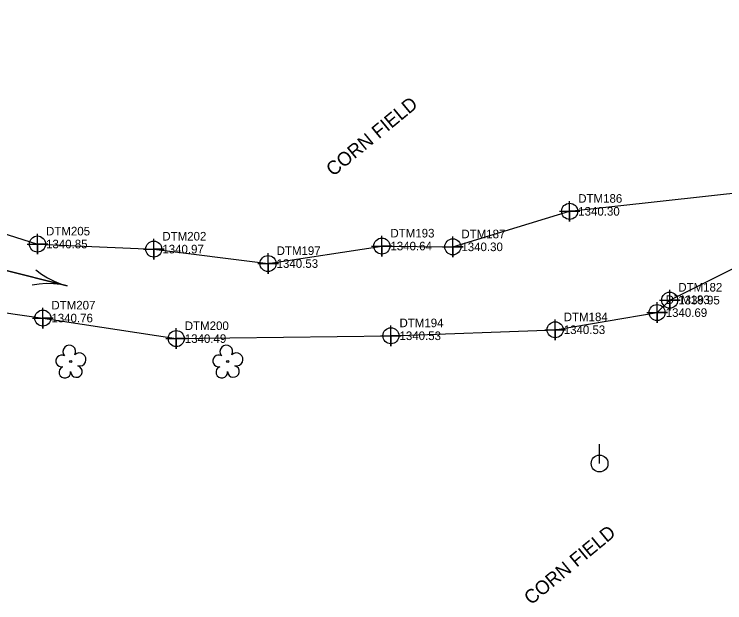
# Model space of a CAD drawing. Extents: x 1435573 to 1437263, y 981340 to 982884.
# Drawn here: x 1436335.7 to 1436542.7, y 982216.7 to 982388.1 of the extents above; entities that cross this region are included whole.
import ezdxf

# ---------------------------------------------------------------- set-up
doc = ezdxf.new("R2010")
doc.units = 0
for name, color, linetype in [('Exist Hydro Jurisdictional Stream or Body of Water', 7, 'Continuous'), ('Exist Hydro River Flow Arrow CELL', 7, 'Continuous'), ('Exist Hydro Stream or Body of Water Cogo Elevation', 7, 'Continuous'), ('Exist Hydro Stream or Body of Water Cogo Number', 7, 'Continuous'), ('Exist Hydro Stream or Body of Water Cogo Point CELL', 7, 'Continuous'), ('Exist Utilities Power Pole CELL', 7, 'Continuous'), ('Exist Vegetation Shrub Text', 7, 'Continuous'), ('Exist Vegetation Tree CELL', 7, 'Continuous')]:
    doc.layers.add(name, color=color, linetype=linetype)

# ---------------------------------------------------------------- blocks, each defined once
blk = doc.blocks.new('EXIST UTILITIES POWER POLE')
at = {"layer": 'Exist Utilities Power Pole CELL'}
for q in [(0, 0.1125), (0, 0)]:
    blk.add_line((0, 0), q, dxfattribs=at)
blk.add_circle((0, 0), 0.049, dxfattribs=at)
blk = doc.blocks.new('EXIST HYDRO RIVER FLOW ARROW')
at = {"layer": 'Exist Hydro River Flow Arrow CELL'}
blk.add_line((0, 0), (0, 0), dxfattribs=at)
blk.add_lwpolyline([(0, 0.04575), (0.03775, 0.03), (0.07725, 0.01725), (0.118, 0.00775), (0.159, 0.0015), (0.2, 0), (-0.2, 0), (0.2, 0), (0.159, -0.0015), (0.118, -0.00775), (0.07725, -0.01725), (0.03775, -0.03), (0, -0.04575)], dxfattribs=at)

msp = doc.modelspace()

# ---------------------------------------------------------------- linework, layer by layer
at = {"layer": 'Exist Hydro Jurisdictional Stream or Body of Water'}
for points in [[(1436111.15, 982453.74), (1436137.02, 982423.29), (1436156.59, 982404.89), (1436183.39, 982389.76), (1436202.59, 982381.74), (1436230.76, 982371.66), (1436265.68, 982349.11), (1436287.96, 982335.57), (1436310.38, 982331.33), (1436342.49, 982321.19), (1436376.37, 982319.71), (1436409.66, 982315.5), (1436442.82, 982320.6), (1436463.49, 982320.37), (1436497.53, 982330.71), (1436550.33, 982336.59), (1436616.17, 982332.31)], [(1436091.98, 982443.75), (1436118.69, 982406.49), (1436146.13, 982381.57), (1436167.28, 982362.75), (1436182.9, 982351.8), (1436221.27, 982335.17), (1436252.29, 982318.28), (1436286.21, 982313.63), (1436313.86, 982303.99), (1436344.05, 982299.63), (1436382.91, 982293.64), (1436445.46, 982294.47), (1436493.31, 982296.22), (1436523.01, 982301.22), (1436526.68, 982304.85), (1436546.5, 982314.76), (1436602.72, 982314.24)]]:
    msp.add_lwpolyline(points, dxfattribs=at)
at = {"layer": 'Exist Hydro Stream or Body of Water Cogo Point CELL'}
for points in [[(1436494.53, 982330.71), (1436500.53, 982330.71), (1436497.53, 982330.71), (1436497.53, 982327.71), (1436497.53, 982333.71)], [(1436339.49, 982321.19), (1436345.49, 982321.19), (1436342.49, 982321.19), (1436342.49, 982318.19), (1436342.49, 982324.19)], [(1436373.37, 982319.71), (1436379.37, 982319.71), (1436376.37, 982319.71), (1436376.37, 982316.71), (1436376.37, 982322.71)], [(1436439.82, 982320.6), (1436445.82, 982320.6), (1436442.82, 982320.6), (1436442.82, 982317.6), (1436442.82, 982323.6)], [(1436460.49, 982320.37), (1436466.49, 982320.37), (1436463.49, 982320.37), (1436463.49, 982317.37), (1436463.49, 982323.37)], [(1436406.66, 982315.5), (1436412.66, 982315.5), (1436409.66, 982315.5), (1436409.66, 982312.5), (1436409.66, 982318.5)], [(1436523.68, 982304.85), (1436529.68, 982304.85), (1436526.68, 982304.85), (1436526.68, 982301.85), (1436526.68, 982307.85)], [(1436520.01, 982301.22), (1436526.01, 982301.22), (1436523.01, 982301.22), (1436523.01, 982298.22), (1436523.01, 982304.22)], [(1436341.05, 982299.63), (1436347.05, 982299.63), (1436344.05, 982299.63), (1436344.05, 982296.63), (1436344.05, 982302.63)], [(1436490.31, 982296.22), (1436496.31, 982296.22), (1436493.31, 982296.22), (1436493.31, 982293.22), (1436493.31, 982299.22)], [(1436442.46, 982294.47), (1436448.46, 982294.47), (1436445.46, 982294.47), (1436445.46, 982291.47), (1436445.46, 982297.47)], [(1436379.91, 982293.64), (1436385.91, 982293.64), (1436382.91, 982293.64), (1436382.91, 982290.64), (1436382.91, 982296.64)]]:
    msp.add_lwpolyline(points, dxfattribs=at)
for centre in [(1436497.53, 982330.71), (1436342.49, 982321.19), (1436376.37, 982319.71), (1436442.82, 982320.6), (1436463.49, 982320.37), (1436409.66, 982315.5), (1436526.68, 982304.85), (1436523.01, 982301.22), (1436344.05, 982299.63), (1436445.46, 982294.47), (1436493.31, 982296.22), (1436382.91, 982293.64)]:
    msp.add_circle(centre, 2.34, dxfattribs=at)
at = {"layer": 'Exist Vegetation Tree CELL'}
for p, q in [((1436352.16, 982286.97), (1436352.16, 982286.97)), ((1436397.9, 982286.99), (1436397.9, 982286.99))]:
    msp.add_line(p, q, dxfattribs=at)
for centre in [(1436352.16, 982286.97), (1436397.9, 982286.99)]:
    msp.add_circle(centre, 0.326, dxfattribs=at)
for centre, radius, start, end in [((1436351.77, 982289.84), 1.86, 330.1651, 219.7134), ((1436397.51, 982289.86), 1.86, 330.1651, 219.7134), ((1436349.55, 982287.12), 1.73, 62.6636, 279.3457), ((1436354.71, 982287.56), 1.9, 257.1011, 134.1999), ((1436395.29, 982287.14), 1.73, 62.6636, 279.3457), ((1436400.45, 982287.58), 1.9, 257.1011, 134.1999), ((1436350.45, 982283.85), 1.69, 111.5671, 6.231), ((1436353.83, 982284.07), 1.7, 181.2822, 74.56), ((1436396.2, 982283.87), 1.69, 111.5671, 6.231), ((1436399.57, 982284.09), 1.7, 181.2822, 74.56)]:
    msp.add_arc(centre, radius, start, end, dxfattribs=at)

# ---------------------------------------------------------------- block references
at = {"layer": 'Exist Hydro River Flow Arrow CELL', "xscale": 49.99999999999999, "yscale": 50, "rotation": -14.136022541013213}
msp.add_blockref('EXIST HYDRO RIVER FLOW ARROW', (1436341.49, 982311.43), dxfattribs=at)
at = {"layer": 'Exist Utilities Power Pole CELL', "xscale": 50, "yscale": 50}
msp.add_blockref('EXIST UTILITIES POWER POLE', (1436506.25, 982257.26), dxfattribs=at)

# ---------------------------------------------------------------- texts
at = {"layer": 'Exist Hydro Stream or Body of Water Cogo Elevation'}
for s, p in [('1340.30', (1436500.03, 982329.46)), ('1340.85', (1436344.99, 982319.94)), ('1340.64', (1436445.32, 982319.35)), ('1340.30', (1436465.99, 982319.12)), ('1340.97', (1436378.87, 982318.46)), ('1340.53', (1436412.16, 982314.25)), ('1339.95', (1436529.18, 982303.6)), ('1340.76', (1436346.55, 982298.38)), ('1340.69', (1436525.51, 982299.97)), ('1340.53', (1436495.81, 982294.97)), ('1340.49', (1436385.41, 982292.39)), ('1340.53', (1436447.96, 982293.22))]:
    msp.add_text(s, height=2.5, dxfattribs=at).set_placement(p)
at = {"layer": 'Exist Hydro Stream or Body of Water Cogo Number'}
for s, p in [('DTM186', (1436500.03, 982333.21)), ('DTM205', (1436344.99, 982323.69)), ('DTM202', (1436378.87, 982322.21)), ('DTM193', (1436445.32, 982323.1)), ('DTM187', (1436465.99, 982322.87)), ('DTM197', (1436412.16, 982318)), ('DTM182', (1436529.18, 982307.35)), ('DTM183', (1436525.51, 982303.72)), ('DTM207', (1436346.55, 982302.13)), ('DTM184', (1436495.81, 982298.72)), ('DTM194', (1436447.96, 982296.97)), ('DTM200', (1436385.41, 982296.14))]:
    msp.add_text(s, height=2.5, dxfattribs=at).set_placement(p)
at = {"layer": 'Exist Vegetation Shrub Text'}
for p in [(1436428.63, 982340.71), (1436486.3, 982215.92)]:
    msp.add_text('CORN FIELD', height=4, rotation=39.5399, dxfattribs=at).set_placement(p)

doc.saveas('drawing.dxf')
